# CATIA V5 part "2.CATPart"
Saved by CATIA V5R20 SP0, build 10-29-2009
Part number: 2
Material "Steel": density 7860 kg/m3, Young's modulus 2e+11 Pa, Poisson ratio 0.266, thermal expansion 1.17e-05 1/K
Bounding box of the stored display mesh (mm): x -247.807 to 2.998, y -100.843 to 106, z -21 to 58.235
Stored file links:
  E:\Ehsan\Amoozesh\CATIA\CATIA Course\Advanced\Videos\Session-16\2.CATPart
  D:\CATIA V5R20\B20\intel_a\startup\materials\Catalog.CATMaterial
  D:\CATIA V5R20\B20\intel_a\resources\graphic\figures\CATIA_EnvironmentMap_Satin_512x512.jpg
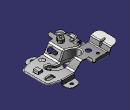
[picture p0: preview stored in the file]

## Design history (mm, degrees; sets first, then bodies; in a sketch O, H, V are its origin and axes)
SheetMetalParameters1: Thickness 2, BendRadius 4, KFactor 0.400515 {= log(min(100,max(20*SheetMetalParameters1.BendRadius,SheetMetalParameters1.Thickness)/SheetMetalParameters1.Thickness))/log(100)/2}, ReliefRadialLength 1, ReliefAxialLength 2, MinimumBendRadius 0
AxisSystem1: origin (0, 0, 0), X (1, 0, 0), Y (0, 1, 0), Z (0, 0, 1)
Body1 (main body), material "Steel"
  Sketch1 on ZX plane of AxisSystem1, origin (0, 0, 0), H (-1, 0, 0), V (0, 0, 1)
    line L1 (0, 0) -> (95.3369, 0)
    point P1 (100, 0)
    line L2 (102.9974, 3.5721) -> (122.1756, 26.4279)
    line L3 (129.8361, 30) -> (205.3369, 30)
    point P2 (205.3369, 30)
    point P3 (95.3369, 10)
    arc A1 centre (95.3369, 10) radius 10 from (95.3369, 0) to (102.9974, 3.5721) ccw
    arc A2 centre (129.8361, 20) radius 10 from (129.8361, 30) to (122.1756, 26.4279) ccw
    angle L1 L2 = 130
    distance L1 L3 = 30
    distance O P1 = 100
    distance P3 P2 H = 110
    radius A1 = 10
    radius A2 = 10 {= Sketch1.radius(A1)}
    horizontal: L1 H, L3 H
    coincidence: L1 P1, L2 P1
    tangency: A1 L1, A1 L2, A2 L3, A2 L2
  d_Extrusion1: Extrude_Thickness 2, Extrude_Profile Sketch1, Extrude_StartLength 100, Extrude_EndLength 100, KFacteur 0.400515 {= log(min(100,max(20*SheetMetalParameters1.BendRadius,SheetMetalParameters1.Thickness)/SheetMetalParameters1.Thickness))/log(100)/2}, Extrude_Radius 4, Extrude_DeductionTable SheetMetalParameters1, Extrude_FixedPoint vertex of Sketch1
  CutOut1: Direction Sketch16, EndLimit through (limit type 2), Orientation true, Profile Sketch16, StartLimit through (limit type 2)
  Sketch2 on face of d_Extrusion1, origin (-185.3662, 75.545, 30), H (-1, 0, 0), V (0, 1, 0)
    point P1 (0, 0)
  Hole1: CATSmHoleRadius 0, NewRoot_AttribNormalisation "No Standard", CATSmHoleType 4, CATSmHoleWbType 1, Diameter 10, CATSmHolePoint Sketch2
  Sketch3 on face of d_Extrusion1, origin (-175.1212, 45.9441, 30), H (-1, 0, 0), V (0, 1, 0)
    point P1 (0, 0)
  Hole2: CATSmHoleRadius 0, CATSmHoleWbType 1, CATSmHoleType 4, Diameter 20, CATSmHolePoint Sketch3, NewRoot_AttribNormalisation "No Standard"
  d_NewWallOnEdge1: NewWallOnEdge_Length 15, KFacteur 0.400515 {= log(min(100,max(20*d_NewWallOnEdge1.Radius,SheetMetalParameters1.Thickness)/SheetMetalParameters1.Thickness))/log(100)/2}, NewWallOnEdge_HeightLimitOffset 0, NewWallOnEdge_WidthOffset1 0, NewWallOnEdge_WidthOffset2 0, NewWallOnEdge_Angle 90, NewWallOnEdge_BendRadiusValue 4 {= d_NewWallOnEdge1.Clearance}, NewWallOnEdge_BendTable SheetMetalParameters1, NewWallOnEdge_GapValue 0, NewWallOnEdge_Edge (edge [face of d_Extrusion1 | face of d_Extrusion1]; edge [face of d_Extrusion1 | face of CutOut1])
  dMultiCornerRelief1
  Corner1: CornerRadius 10, CornerChamferEdges (edge [face of d_NewWallOnEdge1 | face of d_NewWallOnEdge1]; edge [face of d_NewWallOnEdge1 | face of d_NewWallOnEdge1])
  Chamfer1: ChamferAngle 45, ChamferLength1 5, ChamferLength2 1, ChamferPropagation 1, ChamferReverse false, ChamferType 1, CornerChamferEdges (edge [face of d_NewWallOnEdge1 | face of d_NewWallOnEdge1]; edge [face of d_NewWallOnEdge1 | face of d_NewWallOnEdge1])
  Sketch4 on face of d_Extrusion1, origin (-129.8361, 0, 30), H (-1, 0, 0), V (0, 1, 0)
    line L1 (37.3645, -105.1765) -> (85.5833, -105.1765)
    line L2 (85.5833, -105.1765) -> (85.5833, -55.5195)
    line L3 (85.5833, -55.5195) -> (62.7534, -55.5195)
    line L4 (62.7534, -55.5195) -> (37.3645, -74.7355)
    line L5 (37.3645, -74.7355) -> (37.3645, -105.1765)
    point P6 (63.981, -8.9102)
    line L6 (83.5495, 10.7288) -> (83.5495, -28.5492)
    line L7 (83.5495, -28.5492) -> (44.4124, -28.5492)
    line L8 (44.4124, -28.5492) -> (44.4124, 10.7288)
    line L9 (44.4124, 10.7288) -> (83.5495, 10.7288)
    horizontal: L1 H, L3 H, L7 H, L9 H
    vertical: L2 V, L5 V, L6 V, L8 V
    equidistance: L6 L8 P6, L7 L9 P6
  d_Stamp1: NewRoot_AttribNormalisation "No Standard", Stamp_FilletRadius 3, Stamp_IntersectFilletRadius 2
  Sketch5 on face of d_Extrusion1, origin (-129.8361, 0, 30), H (-1, 0, 0), V (0, 1, 0)
    line L1 (64.6863, -22.5846) -> (64.6863, -63.7846)
    vertical: L1 V
  d_Stamp2: NewRoot_AttribNormalisation "No Standard", Stamp_FilletRadius 3, Stamp_IntersectFilletRadius 2
  Sketch6 on face of d_Stamp1, origin (-167.2005, -105.1765, 20), H (1, 0, 0), V (0, -1, 0)
    arc A1 centre (-54.832, 17.1708) radius 47.4176 from (-42.169, -28.5247) to (-12.1376, -3.4596) ccw
  d_Stamp3: NewRoot_AttribNormalisation "No Standard", Stamp_FilletRadius 3, Stamp_IntersectFilletRadius 2
  d_Stamp4: NewRoot_AttribNormalisation "No Standard", Stamp_FilletRadius 3, Stamp_IntersectFilletRadius 2
  d_Stamp5: NewRoot_AttribNormalisation "No Standard", Stamp_FilletRadius 3, Stamp_IntersectFilletRadius 2
  d_Stamp6: KFacteur 0.400515 {= SheetMetalParameters1.KFactor}, NewRoot_AttribNormalisation "No Standard", Stamp_FilletRadius 1, Stamp_IntersectFilletRadius 2
  d_Stamp7: NewRoot_AttribNormalisation "No Standard", Stamp_FilletRadius 1, Stamp_IntersectFilletRadius 2
  Sketch7 on face of d_Extrusion1, origin (-26.881, -36.6752, 0), H (-1, 0, 0), V (0, 1, 0)
    point P1 (-3.1898, 24.8777)
  d_Stamp8: NewRoot_AttribNormalisation "No Standard", Stamp_FilletRadius 1, Stamp_IntersectFilletRadius 2
  Sketch8 on face of d_Stamp1, origin (-193.4154, -9.0035, 20), H (1, 0, 0), V (0, -1, 0)
    point P1 (0, 0)
  d_Stamp9: KFacteur 0.400515 {= SheetMetalParameters1.KFactor}, NewRoot_AttribNormalisation "No Standard", Stamp_FilletRadius 1, Stamp_IntersectFilletRadius 2
  Sketch9 on face of d_Stamp5, origin (-63.3187, -11.1485, -9), H (1, 0, 0), V (0, -1, 0)
    point P1 (-0.2759, -4.0815)
  d_Stamp10: KFacteur 0.400515 {= SheetMetalParameters1.KFactor}, NewRoot_AttribNormalisation "No Standard", Stamp_FilletRadius 1, Stamp_IntersectFilletRadius 2
  Flange1: Angle 110, KFacteur 0.400515 {= log(min(100,max(20*Flange1.Radius,SheetMetalParameters1.Thickness)/SheetMetalParameters1.Thickness))/log(100)/2}, Length 15, Radius 4, Guide edge [face of d_Extrusion1 | face of d_Extrusion1]
  Flange2: Angle 125, Length 30, Radius 4, Guide edge [face of Flange1 | face of Flange1], KFacteur 0.400515 {= log(min(100,max(20*Flange2.Radius,SheetMetalParameters1.Thickness)/SheetMetalParameters1.Thickness))/log(100)/2}
  Sketch10 on , origin (-215.802, 59.015, 49.0909), H (0.736, 0, -0.677), V (0, 1, 0)
    point P1 (0, 0)
  d_Stamp11: NewRoot_AttribNormalisation "No Standard", Stamp_FilletRadius 1, Stamp_IntersectFilletRadius 2
  Sketch11 on face of d_Extrusion1, origin (-75.1984, -45.7429, 0), H (-1, 0, 0), V (0, 1, 0)
    point P1 (0, 0)
  d_Stamp12: NewRoot_AttribNormalisation "No Standard", Stamp_FilletRadius 1, Stamp_IntersectFilletRadius 2
  Sketch12 on face of d_Extrusion1, origin (0, 0, 0), H (-1, 0, 0), V (0, -1, 0)
    construction line L1 (19.6195, -32.3673) -> (42.4278, -32.3673)
    line L2 (19.6195, -24.2537) -> (42.4278, -24.2537)
    line L3 (42.4278, -40.4809) -> (19.6195, -40.4809)
    arc A1 centre (19.6195, -32.3673) radius 8.1136 from (19.6195, -40.4809) to (19.6195, -24.2537) cw
    line L4 (42.4278, -24.2537) -> (42.4278, -40.4809)
    distance L1 L2 = 8.1136
    horizontal: L1 H
    tangency: A1 L2, A1 L3
    vertical: L4 V
  Sketch13 on face of d_Extrusion1, origin (-60.2145, 0, -50.526), H (0, 1, 0), V (0.6428, 0, -0.766)
    construction line L1 (-49.3164, -83.9777) -> (-26.7379, -83.9777)
    line L2 (-26.7379, -87.9777) -> (-42.5847, -87.9777)
    line L3 (-42.5847, -79.9777) -> (-26.7379, -79.9777)
    arc A1 centre (-49.3164, -83.9777) radius 7.8305 from (-42.5847, -87.9777) to (-42.5847, -79.9777) cw
    arc A2 centre (-26.7379, -83.9777) radius 4 from (-26.7379, -79.9777) to (-26.7379, -87.9777) cw
    radius A1 = 7.8305
    radius A2 = 4
    horizontal: L1 H
    tangency: A2 L2, A2 L3
    parallelism: L2 L3, L2 L1
  Sketch14 on face of d_Extrusion1, origin (0, 0, 0), H (-1, 0, 0), V (0, -1, 0)
    projected curve E1 from Sketch15.S1
  Sketch15 on face of d_Extrusion1, origin (0, 0, 30), H (-1, 0, 0), V (0, -1, 0)
    spline S1 through (63.6645, 7.613) (82.0669, -10.8016) (126.9938, -14.4108) (143.7272, -22.1528)
  Sketch16 on XY plane of AxisSystem1, origin (0, 0, 0), H (-1, 0, 0), V (0, -1, 0)
    point P1 (-15.5925, 125.8373)
    line L1 (-15.5925, 125.8373) -> (-15.5925, 45.5161)
    point P2 (-15.5925, 45.5161)
    line L2 (-15.5925, 45.5161) -> (44.3591, 63.8554)
    line L3 (45.8217, 64.0741) -> (99.3874, 64.0741)
    line L4 (100.1363, 64.1305) -> (140.5344, 70.2506)
    line L5 (144.7855, 75.1941) -> (144.7855, 125.8373)
    point P3 (144.7855, 125.8373)
    line L6 (144.7855, 125.8373) -> (-15.5925, 125.8373)
    arc A1 centre (139.7855, 75.1941) radius 5 from (140.5344, 70.2506) to (144.7855, 75.1941) ccw
    point P4 (140.5344, 70.2506)
    point P5 (144.7855, 75.1941)
    arc A2 centre (99.3874, 69.0741) radius 5 from (99.3874, 64.0741) to (100.1363, 64.1305) ccw
    point P7 (99.3874, 64.0741)
    point P8 (100.1363, 64.1305)
    arc A3 centre (45.8217, 59.0741) radius 5 from (44.3591, 63.8554) to (45.8217, 64.0741) cw
    point P10 (44.3591, 63.8554)
    point P11 (45.8217, 64.0741)
    point P13 (-15.5925, -125.8373)
    point P14 (-15.5925, -45.5161)
    point P15 (144.7855, -125.8373)
    point P16 (140.5344, -70.2506)
    point P17 (144.7855, -75.1941)
    point P19 (99.3874, -64.0741)
    point P20 (100.1363, -64.1305)
    point P22 (44.3591, -63.8554)
    point P23 (45.8217, -64.0741)
    line L7 (-15.5925, -125.8373) -> (-15.5925, -45.5161)
    line L8 (-15.5925, -45.5161) -> (44.3591, -63.8554)
    line L9 (45.8217, -64.0741) -> (99.3874, -64.0741)
    line L10 (100.1363, -64.1305) -> (140.5344, -70.2506)
    line L11 (144.7855, -75.1941) -> (144.7855, -125.8373)
    line L12 (144.7855, -125.8373) -> (-15.5925, -125.8373)
    arc A4 centre (139.7855, -75.1941) radius 5 from (140.5344, -70.2506) to (144.7855, -75.1941) cw
    arc A5 centre (99.3874, -69.0741) radius 5 from (99.3874, -64.0741) to (100.1363, -64.1305) cw
    arc A6 centre (45.8217, -59.0741) radius 5 from (44.3591, -63.8554) to (45.8217, -64.0741) ccw
    radius A1 = 5
    radius A2 = 5 {= Sketch16.radius(A1)}
    radius A3 = 5 {= Sketch16.radius(A1)}
    vertical: L1 V, L5 V
    horizontal: L6 H, L3 H
    tangency: A1 L4, A1 L5, A2 L3, A2 L4, A3 L2, A3 L3
    symmetry: P1 P13 H, P2 P14 H, P3 P15 H, P4 P16 H, P5 P17 H, P7 P19 H, P8 P20 H, P10 P22 H, P11 P23 H, L1 L7 H, L2 L8 H, L3 L9 H, L4 L10 H, L5 L11 H, L6 L12 H, A1 A4 H, A2 A5 H, A3 A6 H
  Sketch17 on , origin (-151.2037, -45.3778, 30), H (-1, 0, 0), V (0, 1, 0)
    point P1 (0, 0)
  d_Stamp13: NewRoot_AttribNormalisation "No Standard", Stamp_FilletRadius 1, Stamp_IntersectFilletRadius 2
  Corner2: CornerRadius 10, CornerChamferEdges (edge [face of CutOut1 | face of d_Extrusion1]; edge [face of d_Extrusion1 | face of CutOut1])
  Flange3: Angle 22.6199 {= 2*atan(Flange3.Radius/Flange3.Length)}, Length 5, Radius 1, Guide (edge [face of d_Extrusion1 | face of CutOut1]; edge [face of d_Extrusion1 | face of Corner2]; edge [face of d_Extrusion1 | face of d_Extrusion1]; edge [face of d_Extrusion1 | face of Corner2]; edge [face of CutOut1 | face of d_Extrusion1]), KFacteur 0.25 {= log(min(100,max(20*Flange3.Radius,SheetMetalParameters1.Thickness)/SheetMetalParameters1.Thickness))/log(100)/2}
  Flange4: Angle 90, Length 15, Radius 1, Guide edge [face of CutOut1 | face of d_Extrusion1], KFacteur 0.25 {= log(min(100,max(20*Flange4.Radius,SheetMetalParameters1.Thickness)/SheetMetalParameters1.Thickness))/log(100)/2}
  Flange5: Angle 90, Length 15, Radius 1, Guide edge [face of CutOut1 | face of d_Extrusion1], KFacteur 0.25 {= log(min(100,max(20*Flange5.Radius,SheetMetalParameters1.Thickness)/SheetMetalParameters1.Thickness))/log(100)/2}
  Flange6: Angle 90, Length 30, Radius 1, Guide edge [face of Flange4 | face of Flange4], KFacteur 0.25 {= log(min(100,max(20*Flange6.Radius,SheetMetalParameters1.Thickness)/SheetMetalParameters1.Thickness))/log(100)/2}
  Flange7: Angle 90, Length 30, Radius 1, Guide edge [face of Flange5 | face of Flange5], KFacteur 0.25 {= log(min(100,max(20*Flange7.Radius,SheetMetalParameters1.Thickness)/SheetMetalParameters1.Thickness))/log(100)/2}
  Corner3: CornerRadius 20, CornerChamferEdges (edge [face of Flange7 | face of Flange7]; edge [face of Flange7 | face of Flange7]; edge [face of Flange6 | face of Flange6]; edge [face of Flange6 | face of Flange6]; edge [face of Flange2 | face of Flange2]; edge [face of Flange2 | face of Flange2])
  CutOut2: Direction Sketch18, EndLimit through (limit type 2), Orientation true, Profile Sketch18, StartLimit through (limit type 2)
  Corner4: CornerRadius 10, CornerChamferEdges edge [face of d_Stamp1 | face of d_Stamp1]
  Chamfer2: ChamferAngle 45, ChamferLength1 10, ChamferLength2 1, ChamferPropagation 1, ChamferReverse false, ChamferType 1, CornerChamferEdges edge [face of CutOut1 | face of d_Extrusion1]
  Sketch18 on face of Flange6, origin (0, 0, -19), H (1, 0, 0), V (0, 1, 0)
    circle A1 centre (-70.1747, -82.4655) radius 6.0052
    circle A2 centre (-70.1747, 82.4655) radius 6.0052
    circle A3 centre (-110.7135, 13.1664) radius 7.4242
    symmetry: A1 A2 H
Body2 "Punch"
  Sketch19 on XY plane of AxisSystem1, origin (0, 0, 0), H (0, -1, 0), V (-1, 0, 0)
    point P1 (-5.7735, -10)
    point P2 (5.7735, -10)
    point P3 (11.547, 0)
    point P4 (5.7735, 10)
    point P5 (-5.7735, 10)
    point P6 (-11.547, 0)
    point P7 (0, -10)
    line L1 (-5.7735, -10) -> (5.7735, -10)
    line L2 (5.7735, -10) -> (11.547, 0)
    line L3 (11.547, 0) -> (5.7735, 10)
    line L4 (5.7735, 10) -> (-5.7735, 10)
    line L5 (-5.7735, 10) -> (-11.547, 0)
    line L6 (-11.547, 0) -> (-5.7735, -10)
    construction line L7 (0, 0) -> (0, -10)
    construction circle A1 centre (0, 0) radius 11.547
    construction arc A2 centre (-5.7735, 10) radius 11.547 from (5.7735, 10) to (-11.547, 0) cw
    construction arc A3 centre (5.7735, -10) radius 11.547 from (11.547, 0) to (-5.7735, -10) ccw
    circle A4 centre (0, 0) radius 4
    distance L1 L4 = 20
    radius A4 = 4
    vertical: L7 V
    coincidence: A1 P1, A1 P2, A1 P3, A1 P4, A1 P5, A1 P6, A2 O, A3 O
    midpoint: P7 L1
  Pad1: profile Sketch19, direction (0, 0, 1), length 15, mirrored extent
  Pocket1: profile sketch element, length 15, opposite side length -7.5
  Fillet1: radius 2, on edge [end face of Pad1 | face of Pad1 from Sketch19.L1]; edge [end face of Pad1 | face of Pad1 from Sketch19.L5]; edge [end face of Pad1 | face of Pad1 from Sketch19.L4]; edge [end face of Pad1 | face of Pad1 from Sketch19.L3]; edge [end face of Pad1 | face of Pad1 from Sketch19.L2]; edge [face of Pad1 from Sketch19.L1 | face of Pad1 from Sketch19.L2]; edge [face of Pad1 from Sketch19.L2 | face of Pad1 from Sketch19.L3]; edge [face of Pad1 from Sketch19.L3 | face of Pad1 from Sketch19.L4]; edge [face of Pad1 from Sketch19.L4 | face of Pad1 from Sketch19.L5]
  Fillet2: radius 1, on edge [face of Pocket1 | end face of Pad1]; start face of Pocket1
